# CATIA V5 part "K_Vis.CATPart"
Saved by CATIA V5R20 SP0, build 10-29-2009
Part number: Vis
Bounding box of the stored display mesh (mm): x -50.643 to 50.643, y 301.5 to 608.5, z 30 to 45
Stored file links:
  G:\Khaled_CFAO_2011\SIL\SIL_GR2\ahabrial\ahabrial\Khaled\CAD_ThinkMOTION\K_Vis.CATPart
  G:\Données\Ecole\IFMA\2A\Thinkmotion2\Etape18\trotinette.CATProduct
  G:\Khaled_CFAO_2011\SIL\SIL_GR2\ahabrial\ahabrial\Khaled\CAD_ThinkMOTION\K_arriere.CATPart
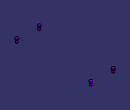
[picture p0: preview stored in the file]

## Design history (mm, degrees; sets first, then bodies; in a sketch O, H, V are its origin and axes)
External parameters (linked from other documents)
  External.Diametre_vis_accroche = 10 mm
Set1
  DatumSurface1: linked copy from another document
  DatumCurve1: linked copy from another document
  DatumSurface2: linked copy from another document
  Line1 "Droite_arriere": linked copy from another document
Body1 (main body)
  Sketch1 on face of DatumSurface1, origin (0, 0, 40), H (1, 0, 0), V (0, -1, 0)
    circle A1 centre (44.6429, -602.5) radius 5
    reference projected circle E1 centre (44.6429, -602.5) radius 5 from edge of DatumCurve1
    construction line L1 (0, -600) -> (0, -630)
    reference projected line E2 (0, -200) -> (0, -700) from Line1
    circle A2 centre (-44.6429, -602.5) radius 5
    axis line L2 (-30, -455) -> (30, -455)
    reference projected line E3 (69.6429, -590) -> (36.3095, -590) from edge of DatumSurface1
    circle A3 centre (-44.6429, -307.5) radius 5
    circle A4 centre (44.6429, -307.5) radius 5
    radius A1 = 5 {= External.Diametre_vis_accroche /2}
    distance L2 E3 = 135 {= 270mm/2}
    concentricity: A1 E1
    vertical: L1 V
    coincidence: L1 E2
    symmetry: A1 A2 L1, A2 A3 L2, A3 A4 L1
    horizontal: L2 H
  Pad1: profile Sketch1, direction (0, 0, -1), up to face of DatumSurface2
  Sketch2 on start face of Pad1, origin (0, 0, 40), H (1, 0, 0), V (0, 1, 0)
    circle A1 centre (44.6429, 602.5) radius 6
    reference projected circle E1 centre (44.6429, 602.5) radius 5 from edge of DatumCurve1
    circle A2 centre (44.6429, 307.5) radius 6
    reference projected circle E2 centre (44.6429, 307.5) radius 5 from edge [start face of Pad1 | face of Pad1 from Sketch1.A4]
    circle A3 centre (-44.6429, 307.5) radius 6
    reference projected circle E3 centre (-44.6429, 307.5) radius 5 from edge [start face of Pad1 | face of Pad1 from Sketch1.A3]
    circle A4 centre (-44.6429, 602.5) radius 6
    reference projected circle E4 centre (-44.6429, 602.5) radius 5 from edge [start face of Pad1 | face of Pad1 from Sketch1.A2]
    radius A1 = 6 {= (External.Diametre_vis_accroche +2mm)/2}
    concentricity: E1 A1, E2 A2, A3 E3, A4 E4
  Pad2: profile Sketch2, direction (0, 0, 1), length 5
